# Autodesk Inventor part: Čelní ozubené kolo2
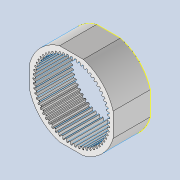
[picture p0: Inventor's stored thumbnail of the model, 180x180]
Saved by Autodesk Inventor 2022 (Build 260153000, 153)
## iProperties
CustomPartVersion: 1
Created: 2025-05
Part Number: Čelní ozubené kolo2
Material: Všeobecné
Document SubType Name: Modeling
Designer: jbart
Categories: <?xml version="1.0" encoding="UTF-16"?> <MemberInstance><Categories><FamilyTemplate><FamilyTemplateParameter ValueType="xs:double" Id="1" ObjectReferenceKey="da
Density: 1 g/cm^3
Appearance: Výchozí
Mass: 5966.28 g
Surface Area: 6901.86 cm^2
Volume: 5966.28 cm^3
Author: jbart
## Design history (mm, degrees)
sketch "Sketch1"
  geometry: C1 r 210 at (0, 0)
  constraints: 1 centre point
  dimensions: "d0" = 420 diameter of C1
extrude "Extrusion1" new body sketch "Sketch1" distance "d1" = 180 (= da_b); taper "d2" = 0 deg
workplane "Work Plane2"
sketch "Sketch2"
  geometry: C1 r 210 at (0, 0) reference; C2 r 180 at (0, 0)
  constraints: 1 centre point, 1 coincident
  dimensions: "d3" = 360 diameter of C2 (= da_d)
feature "Roztečný průměr" sketch "Sketch2" dims "d4" = 10, "d5" = 0
workplane "Work Plane8"
workplane "Work Plane9"
feature "Čelní ozubené kolo" dims "da_b" = 180, "da_d" = 360, "da_z" = 600, "da_aw" = 125.36534, "da_da" = 349.09631, "da_df" = 373.75525, "da_dw" = 358.18668, "da_z2" = 180, "da_beta" = 0, "da_lefttooth" = 0, "da_righttooth" = 0, "da_straighttooth" = 10
chamfer "Zkosení1" distance "d60" = 1; stored, may be unused: second distance "d61" = 2, angle "d62" = 45 deg
chamfer "Zkosení2" distance "d64" = 1; stored, may be unused: second distance "d65" = 2, angle "d66" = 45 deg
sketch "Náčrt5"
  geometry: L1 (0, 0)-(0, 50); L2 (-150, 222)-(150, 222); L3 (150, 222)-(150, 202); L4 (150, 202)-(-150, 202); L5 (-150, 202)-(-150, 222)
  constraints: 10 end point, 2 parallel, 1 horizontal, 1 perpendicular, 1 vertical, 1 other
  dimensions: "d67" = 50 distance of L1.start L1.end; "d68" = 300 distance of L3.end L4.end; "d69" = 20 distance of L2.end L3.end; "d70" = 202 distance from line of L1.start L4
extrude "Vysunutí3" cut sketch "Náčrt5" extent not by distance; stored distance "d71" = 0; taper "d72" = 0 deg
pattern_circular "Kruhové pole2" dims angle "d74" = 360 deg
body "Solid1"
body "Srf1"
other parameters: "d16" = 125.36534 (= da_aw), "d17" = 0, "d34" = 3 deg (computed from da_z), "d39" = 0, "d45" = 0, "d47" = 125.36534 (= da_aw), "d50" = 0, "d51" = 0, "d52" = 125.36534 (= da_aw)
